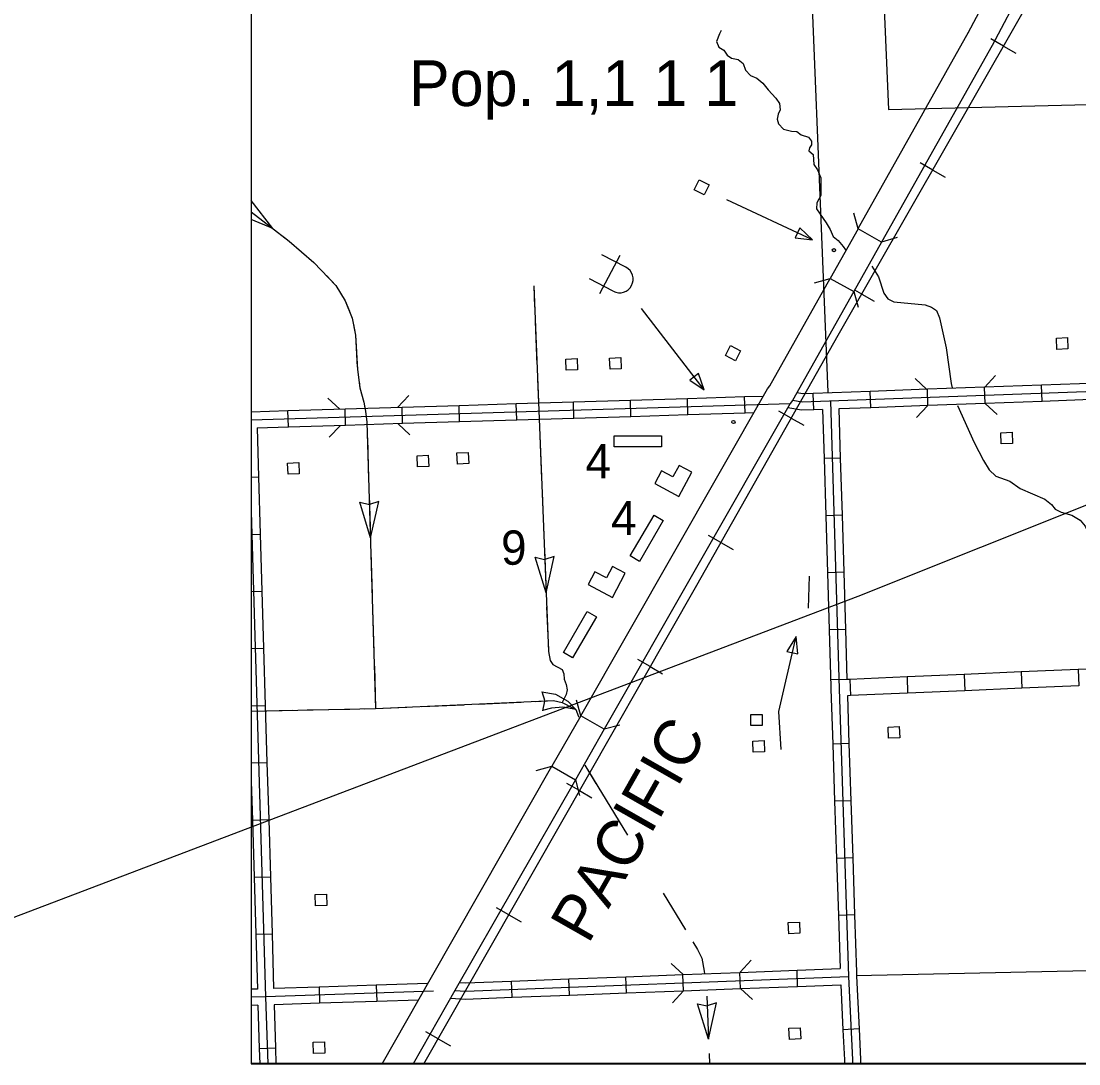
# Model space of a CAD drawing. Extents: x -0.3 to 2.65, y 0 to 1.9.
# Drawn here: x 0.3593 to 0.4763, y 0.1443 to 0.2596 of the extents above; entities that cross this region are included whole.
import ezdxf

# ---------------------------------------------------------------- set-up
doc = ezdxf.new("R2010")
doc.units = 0
for name, color, linetype in [('Default', 7, 'Continuous'), ('DSN_DRFT_DNC', 7, 'Continuous'), ('Level 12', 7, 'Continuous'), ('Level 14', 7, 'Continuous'), ('Level 15', 7, 'Continuous'), ('Level 19', 7, 'Continuous'), ('Level 20', 7, 'Continuous'), ('Level 27', 7, 'Continuous'), ('Level 28', 7, 'Continuous'), ('Level 29', 7, 'Continuous'), ('Level 30', 7, 'Continuous'), ('Level 31', 7, 'Continuous'), ('Level 32', 7, 'Continuous'), ('Level 6', 7, 'Continuous')]:
    doc.layers.add(name, color=color, linetype=linetype)

msp = doc.modelspace()

# ---------------------------------------------------------------- linework, layer by layer
at = {"layer": 'Default'}
msp.add_line((0.34423, 0.15508), (0.45189, 0.196), dxfattribs=at)
msp.add_lwpolyline([(0.45189, 0.196), (0.68371, 0.28858), (0.61638, 0.27038)], dxfattribs=at)
at = {"layer": 'DSN_DRFT_DNC'}
msp.add_lwpolyline([(0.38477, 0.54167), (1.0319, 0.54167), (1.0319, 0.1443), (0.38477, 0.1443)], close=True, dxfattribs=at)
at = {"layer": 'Level 12'}
for p, q in [((0.38713, 0.23666), (0.38476, 0.23975)), ((0.38476, 0.23848), (0.38713, 0.23666)), ((0.38713, 0.23666), (0.38476, 0.23764)), ((0.39675, 0.20639), (0.39782, 0.20614)), ((0.39794, 0.20246), (0.39675, 0.20639)), ((0.39888, 0.20646), (0.39783, 0.20614)), ((0.39794, 0.20246), (0.39888, 0.20646)), ((0.41615, 0.2003), (0.41721, 0.20006)), ((0.41737, 0.19638), (0.41615, 0.2003)), ((0.41827, 0.20038), (0.41723, 0.20006)), ((0.41737, 0.19638), (0.41827, 0.20038)), ((0.41691, 0.18544), (0.41724, 0.1844)), ((0.417, 0.18332), (0.41724, 0.18439)), ((0.43624, 0.15101), (0.43519, 0.15068)), ((0.43533, 0.147), (0.43624, 0.15101)), ((0.43411, 0.15092), (0.43518, 0.15068)), ((0.43533, 0.147), (0.43411, 0.15092)), ((0.4354, 0.14542), (0.43544, 0.14427))]:
    msp.add_line(p, q, dxfattribs=at)
for points in [[(0.38838, 0.2357), (0.38895, 0.23526), (0.39168, 0.2329), (0.39197, 0.2326)], [(0.39306, 0.23146), (0.39411, 0.23035), (0.39515, 0.22867), (0.39561, 0.22752)], [(0.416, 0.23031), (0.4161, 0.22794)], [(0.39606, 0.22602), (0.39629, 0.22484), (0.39648, 0.22131)], [(0.41616, 0.22636), (0.41635, 0.22163)], [(0.41642, 0.22005), (0.41653, 0.21736)], [(0.39668, 0.21974), (0.39678, 0.21905), (0.3972, 0.21744), (0.39733, 0.21677)], [(0.3976, 0.21351), (0.39774, 0.20878)], [(0.41667, 0.21374), (0.41686, 0.209)], [(0.39779, 0.2072), (0.39794, 0.20246)], [(0.41692, 0.20742), (0.41712, 0.20269)], [(0.39798, 0.20088), (0.39813, 0.19614)], [(0.41718, 0.20111), (0.41737, 0.19638)], [(0.39818, 0.19457), (0.39832, 0.18983)], [(0.41743, 0.1948), (0.41762, 0.19006)], [(0.41763, 0.18986), (0.41781, 0.18889), (0.41812, 0.18845), (0.41914, 0.18788), (0.41934, 0.18742), (0.41938, 0.18682), (0.41958, 0.18624), (0.41969, 0.18562), (0.41961, 0.18511), (0.41915, 0.18424), (0.41953, 0.18404), (0.42006, 0.18374), (0.42067, 0.18345), (0.42097, 0.18268), (0.42101, 0.18263)], [(0.39837, 0.18825), (0.39851, 0.18356)], [(0.4169, 0.18543), (0.41842, 0.18514), (0.41979, 0.18438), (0.42066, 0.18345), (0.41921, 0.18373), (0.41796, 0.18361), (0.41698, 0.18334)], [(0.39725, 0.18353), (0.39851, 0.18356), (0.40198, 0.18371)], [(0.40356, 0.18378), (0.40829, 0.18399)], [(0.40987, 0.18406), (0.4146, 0.18428)], [(0.41618, 0.18435), (0.4182, 0.18444), (0.41915, 0.18424)], [(0.38632, 0.18331), (0.38935, 0.18337)], [(0.39093, 0.18341), (0.39567, 0.1835)], [(0.42165, 0.17729), (0.42289, 0.17527)], [(0.43031, 0.16314), (0.43278, 0.1591)], [(0.43361, 0.15775), (0.43412, 0.15692), (0.43461, 0.15595), (0.43487, 0.15451), (0.4349, 0.15424)], [(0.43514, 0.15174), (0.43533, 0.147)]]:
    msp.add_lwpolyline(points, dxfattribs=at)
at = {"layer": 'Level 14'}
for points in [[(0.43675, 0.25856), (0.43655, 0.25819), (0.43624, 0.25733), (0.4365, 0.25671), (0.43705, 0.25637), (0.43739, 0.25583), (0.43789, 0.25549), (0.43863, 0.25534), (0.43916, 0.25492), (0.43943, 0.25417), (0.44, 0.25358), (0.44069, 0.25329), (0.44135, 0.25273), (0.44193, 0.25198), (0.44279, 0.25108), (0.4432, 0.25047), (0.44325, 0.24979), (0.44306, 0.24931), (0.44294, 0.24874), (0.44308, 0.24822), (0.44363, 0.24764), (0.44452, 0.24741), (0.44511, 0.24739), (0.4456, 0.24701), (0.44639, 0.24675), (0.44675, 0.24632), (0.44675, 0.2459), (0.44651, 0.24559), (0.44642, 0.24525), (0.44691, 0.24483), (0.44699, 0.24372), (0.4474, 0.24313), (0.44776, 0.24224), (0.44776, 0.24032), (0.44732, 0.2395), (0.4473, 0.23883), (0.44836, 0.23729), (0.44879, 0.23654), (0.44913, 0.23576), (0.44969, 0.23533), (0.45025, 0.23465), (0.45049, 0.23429)], [(0.38476, 0.23848), (0.38895, 0.23526), (0.39168, 0.2329), (0.39411, 0.23035), (0.39515, 0.22867), (0.39592, 0.22675), (0.39629, 0.22484), (0.3965, 0.22105), (0.39678, 0.21905), (0.3972, 0.21744), (0.39739, 0.21645), (0.39755, 0.21522), (0.39851, 0.18356)], [(0.38476, 0.23848), (0.38895, 0.23526), (0.39168, 0.2329), (0.39411, 0.23035), (0.39515, 0.22867), (0.39592, 0.22675), (0.39629, 0.22484), (0.3965, 0.22105), (0.39678, 0.21905), (0.3972, 0.21744), (0.39739, 0.21645), (0.39755, 0.21522), (0.39851, 0.18356)], [(0.45341, 0.23248), (0.45416, 0.23132), (0.45474, 0.2295), (0.45516, 0.22889), (0.45586, 0.22853), (0.45929, 0.22821), (0.46002, 0.22797), (0.46055, 0.22757), (0.46088, 0.22679), (0.46163, 0.22347), (0.46217, 0.21953), (0.46229, 0.21903)], [(0.416, 0.23031), (0.41763, 0.18986)], [(0.416, 0.23031), (0.41763, 0.18986)], [(0.4629, 0.21707), (0.46472, 0.21299), (0.46575, 0.211), (0.46638, 0.20997), (0.46714, 0.20926), (0.46867, 0.2087), (0.46982, 0.20789), (0.47256, 0.20672), (0.47328, 0.20613), (0.47369, 0.20563), (0.47436, 0.20528), (0.47552, 0.20495), (0.47644, 0.20439), (0.477, 0.20374), (0.47783, 0.20192), (0.47826, 0.20143), (0.47916, 0.20095)], [(0.38476, 0.18328), (0.39851, 0.18356), (0.4182, 0.18444), (0.41915, 0.18424)], [(0.38476, 0.18328), (0.39851, 0.18356), (0.4182, 0.18444), (0.41915, 0.18424)], [(0.42165, 0.17729), (0.42638, 0.16956)], [(0.42165, 0.17729), (0.42638, 0.16956)]]:
    msp.add_lwpolyline(points, dxfattribs=at)
at = {"layer": 'Level 15'}
for p, q in [((0.45962, 0.21707), (0.45955, 0.21887)), ((0.46593, 0.21731), (0.46586, 0.2191)), ((0.47224, 0.21754), (0.47218, 0.21933)), ((0.42676, 0.21588), (0.4267, 0.21767)), ((0.43307, 0.21607), (0.43302, 0.21786)), ((0.43939, 0.21626), (0.43933, 0.21806)), ((0.44699, 0.21661), (0.44692, 0.2184)), ((0.4533, 0.21684), (0.45324, 0.21863)), ((0.38476, 0.21548), (0.44439, 0.2173)), ((0.38476, 0.21639), (0.38881, 0.21651)), ((0.38887, 0.21472), (0.38881, 0.21651)), ((0.39518, 0.21491), (0.39513, 0.21671)), ((0.4015, 0.21511), (0.40144, 0.2169)), ((0.40781, 0.2153), (0.40776, 0.21709)), ((0.41413, 0.21549), (0.41407, 0.21729)), ((0.42044, 0.21568), (0.42039, 0.21748)), ((0.44992, 0.21126), (0.44812, 0.21121)), ((0.38476, 0.20916), (0.38556, 0.20918)), ((0.45011, 0.20495), (0.44831, 0.20489)), ((0.38476, 0.20283), (0.38575, 0.20286)), ((0.4503, 0.19863), (0.4485, 0.19858)), ((0.38476, 0.19651), (0.38593, 0.19655)), ((0.45049, 0.19232), (0.44869, 0.19226)), ((0.38476, 0.19019), (0.38612, 0.19023)), ((0.46361, 0.18734), (0.46369, 0.18554)), ((0.46992, 0.18761), (0.47, 0.18582)), ((0.47623, 0.18788), (0.47631, 0.18609)), ((0.45065, 0.18679), (0.44886, 0.18673)), ((0.45098, 0.18679), (0.45106, 0.185)), ((0.4573, 0.18707), (0.45737, 0.18527)), ((0.38476, 0.18387), (0.38631, 0.18392)), ((0.45088, 0.17969), (0.44909, 0.17963)), ((0.38476, 0.17755), (0.38649, 0.1776)), ((0.38476, 0.17548), (0.38489, 0.17123)), ((0.45109, 0.17337), (0.44929, 0.17332)), ((0.38489, 0.17123), (0.38668, 0.17129)), ((0.45129, 0.16706), (0.4495, 0.167)), ((0.38507, 0.16492), (0.38687, 0.16497)), ((0.4515, 0.16075), (0.44971, 0.16069)), ((0.38526, 0.1586), (0.38705, 0.15866)), ((0.4452, 0.15284), (0.44513, 0.15464)), ((0.41363, 0.15163), (0.41356, 0.15343)), ((0.41995, 0.15188), (0.41988, 0.15367)), ((0.42626, 0.15212), (0.42619, 0.15391)), ((0.43257, 0.15236), (0.4325, 0.15415)), ((0.43889, 0.1526), (0.43882, 0.15439)), ((0.38544, 0.15254), (0.38476, 0.15253)), ((0.39226, 0.15276), (0.39232, 0.15097)), ((0.39857, 0.15297), (0.39863, 0.15118)), ((0.38549, 0.15075), (0.38476, 0.15073)), ((0.452, 0.14813), (0.45021, 0.14805)), ((0.38564, 0.14597), (0.38744, 0.14603)), ((0.38564, 0.14597), (0.3857, 0.14427)), ((0.38744, 0.14603), (0.38749, 0.14427))]:
    msp.add_line(p, q, dxfattribs=at)
for points in [[(0.50863, 0.219), (0.50657, 0.21948), (0.50035, 0.21945), (0.44569, 0.21744), (0.44464, 0.21764)], [(0.45955, 0.21887), (0.45324, 0.21863)], [(0.46586, 0.2191), (0.45955, 0.21887)], [(0.47218, 0.21933), (0.46586, 0.2191)], [(0.47849, 0.21956), (0.47218, 0.21933)], [(0.42039, 0.21748), (0.4267, 0.21767)], [(0.4267, 0.21767), (0.43302, 0.21786)], [(0.43302, 0.21786), (0.43933, 0.21806)], [(0.43933, 0.21806), (0.44141, 0.21812)], [(0.44692, 0.2184), (0.44576, 0.21836), (0.44511, 0.21848)], [(0.45324, 0.21863), (0.44692, 0.2184)], [(0.47856, 0.21777), (0.47224, 0.21754)], [(0.38881, 0.21651), (0.39513, 0.21671)], [(0.39513, 0.21671), (0.40144, 0.2169)], [(0.40144, 0.2169), (0.40776, 0.21709)], [(0.40776, 0.21709), (0.41407, 0.21729)], [(0.41407, 0.21729), (0.42039, 0.21748)], [(0.44699, 0.21661), (0.44562, 0.21656), (0.44413, 0.21684)], [(0.44796, 0.21664), (0.44699, 0.21661)], [(0.44796, 0.21664), (0.44812, 0.21121)], [(0.44885, 0.21755), (0.4498, 0.18573), (0.45084, 0.15394), (0.45128, 0.14472), (0.45128, 0.14427)], [(0.4533, 0.21684), (0.44975, 0.21671)], [(0.44975, 0.21671), (0.44992, 0.21126)], [(0.45962, 0.21707), (0.4533, 0.21684)], [(0.46593, 0.21731), (0.45962, 0.21707)], [(0.47224, 0.21754), (0.46593, 0.21731)], [(0.40781, 0.2153), (0.41413, 0.21549)], [(0.41413, 0.21549), (0.42044, 0.21568)], [(0.42044, 0.21568), (0.42676, 0.21588)], [(0.42676, 0.21588), (0.43307, 0.21607)], [(0.43307, 0.21607), (0.43939, 0.21626)], [(0.43939, 0.21626), (0.44037, 0.21629)], [(0.3854, 0.21461), (0.38887, 0.21472)], [(0.3854, 0.21461), (0.38556, 0.20918)], [(0.38887, 0.21472), (0.39518, 0.21491)], [(0.39518, 0.21491), (0.4015, 0.21511)], [(0.4015, 0.21511), (0.40781, 0.2153)], [(0.44812, 0.21121), (0.44831, 0.20489)], [(0.44992, 0.21126), (0.45011, 0.20495)], [(0.38556, 0.20918), (0.38575, 0.20286)], [(0.38476, 0.20532), (0.38634, 0.15168), (0.38658, 0.14427)], [(0.44831, 0.20489), (0.4485, 0.19858)], [(0.45011, 0.20495), (0.4503, 0.19863)], [(0.38575, 0.20286), (0.38593, 0.19655)], [(0.4485, 0.19858), (0.44869, 0.19226)], [(0.4503, 0.19863), (0.45049, 0.19232)], [(0.38593, 0.19655), (0.38612, 0.19023)], [(0.44869, 0.19226), (0.44888, 0.18595)], [(0.45049, 0.19232), (0.45065, 0.18678)], [(0.38612, 0.19023), (0.38631, 0.18392)], [(0.46361, 0.18734), (0.4573, 0.18707)], [(0.46992, 0.18761), (0.46361, 0.18734)], [(0.47623, 0.18788), (0.46992, 0.18761)], [(0.48254, 0.18815), (0.47623, 0.18788)], [(0.45098, 0.18679), (0.45065, 0.18678)], [(0.4573, 0.18707), (0.45098, 0.18679)], [(0.47631, 0.18609), (0.47, 0.18582)], [(0.44888, 0.18595), (0.44889, 0.1857), (0.44909, 0.17963)], [(0.45106, 0.185), (0.45071, 0.18499)], [(0.45071, 0.18499), (0.45088, 0.17969)], [(0.45737, 0.18527), (0.45106, 0.185)], [(0.46369, 0.18554), (0.45737, 0.18527)], [(0.47, 0.18582), (0.46369, 0.18554)], [(0.38631, 0.18392), (0.38649, 0.1776)], [(0.44909, 0.17963), (0.44929, 0.17332)], [(0.45088, 0.17969), (0.45109, 0.17337)], [(0.38649, 0.1776), (0.38668, 0.17129)], [(0.44929, 0.17332), (0.4495, 0.167)], [(0.45109, 0.17337), (0.45129, 0.16706)], [(0.38489, 0.17123), (0.38507, 0.16492)], [(0.38668, 0.17129), (0.38687, 0.16497)], [(0.4495, 0.167), (0.44971, 0.16069)], [(0.45129, 0.16706), (0.4515, 0.16075)], [(0.38507, 0.16492), (0.38526, 0.1586)], [(0.38687, 0.16497), (0.38705, 0.15866)], [(0.44971, 0.16069), (0.4499, 0.15482)], [(0.4515, 0.16075), (0.45171, 0.15443)], [(0.38526, 0.1586), (0.38544, 0.15254)], [(0.38705, 0.15866), (0.38723, 0.15259)], [(0.43882, 0.15439), (0.44513, 0.15464)], [(0.44513, 0.15464), (0.4499, 0.15482)], [(0.40729, 0.15238), (0.40846, 0.15232), (0.45084, 0.15394)], [(0.40779, 0.15327), (0.40847, 0.15323), (0.41356, 0.15343)], [(0.41356, 0.15343), (0.41988, 0.15367)], [(0.41988, 0.15367), (0.42619, 0.15391)], [(0.42619, 0.15391), (0.4325, 0.15415)], [(0.4325, 0.15415), (0.43882, 0.15439)], [(0.45171, 0.15443), (0.45172, 0.15397), (0.452, 0.14813)], [(0.40492, 0.1523), (0.38634, 0.15168), (0.38476, 0.15165)], [(0.39226, 0.15276), (0.38723, 0.15259)], [(0.39857, 0.15297), (0.39226, 0.15276)], [(0.40429, 0.15316), (0.39857, 0.15297)], [(0.41995, 0.15188), (0.42626, 0.15212)], [(0.42626, 0.15212), (0.43257, 0.15236)], [(0.43257, 0.15236), (0.43889, 0.1526)], [(0.43889, 0.1526), (0.4452, 0.15284)], [(0.4452, 0.15284), (0.44997, 0.15302)], [(0.44997, 0.15302), (0.45021, 0.14805)], [(0.39232, 0.15097), (0.38729, 0.1508)], [(0.39863, 0.15118), (0.39232, 0.15097)], [(0.40325, 0.15133), (0.39863, 0.15118)], [(0.4068, 0.15152), (0.40846, 0.15144), (0.41363, 0.15163)], [(0.41363, 0.15163), (0.41995, 0.15188)], [(0.38549, 0.15075), (0.38564, 0.14597)], [(0.38729, 0.1508), (0.38744, 0.14603)], [(0.45021, 0.14805), (0.45037, 0.1447), (0.45037, 0.14427)], [(0.452, 0.14813), (0.45216, 0.14475), (0.45217, 0.14427)]]:
    msp.add_lwpolyline(points, dxfattribs=at)
at = {"layer": 'Level 19'}
for points in [[(0.43485, 0.24037), (0.43374, 0.24094), (0.43432, 0.24205), (0.43543, 0.24148)], [(0.44544, 0.23672), (0.44492, 0.23561), (0.44684, 0.23539)], [(0.43831, 0.22203), (0.43721, 0.22261), (0.43779, 0.22372), (0.43889, 0.22314)], [(0.47387, 0.22329), (0.47382, 0.22454), (0.47507, 0.22459), (0.47511, 0.22334)], [(0.42445, 0.22109), (0.4244, 0.22233), (0.42565, 0.22238), (0.42569, 0.22113)], [(0.4196, 0.22097), (0.41955, 0.22222), (0.4208, 0.22226), (0.42085, 0.22102)], [(0.43422, 0.22063), (0.43326, 0.21988), (0.43486, 0.2188)], [(0.42491, 0.21252), (0.42491, 0.21372), (0.43015, 0.21372), (0.43015, 0.21252)], [(0.46772, 0.21283), (0.46767, 0.21407), (0.46892, 0.21412), (0.46896, 0.21287)], [(0.40756, 0.21061), (0.40751, 0.21185), (0.40876, 0.2119), (0.40881, 0.21066)], [(0.38883, 0.20947), (0.38878, 0.21072), (0.39003, 0.21076), (0.39007, 0.20952)], [(0.40314, 0.21029), (0.40309, 0.21153), (0.40434, 0.21158), (0.40439, 0.21034)], [(0.42771, 0.19983), (0.42668, 0.20044), (0.42931, 0.20496), (0.43034, 0.20436)], [(0.42031, 0.18917), (0.41928, 0.18977), (0.42191, 0.1943), (0.42294, 0.1937)], [(0.44402, 0.18988), (0.44521, 0.18961), (0.44502, 0.19153)], [(0.44003, 0.18168), (0.44003, 0.18292), (0.44128, 0.18292), (0.44128, 0.18168)], [(0.45525, 0.18028), (0.4552, 0.18152), (0.45645, 0.18157), (0.4565, 0.18033)], [(0.44027, 0.17873), (0.44023, 0.17997), (0.44148, 0.18002), (0.44152, 0.17878)], [(0.39187, 0.16175), (0.39182, 0.16299), (0.39307, 0.16304), (0.39311, 0.1618)], [(0.44421, 0.15866), (0.44416, 0.15991), (0.44541, 0.15995), (0.44546, 0.15871)], [(0.44429, 0.14698), (0.44424, 0.14822), (0.44549, 0.14827), (0.44554, 0.14703)], [(0.39164, 0.14543), (0.39159, 0.14667), (0.39284, 0.14672), (0.39289, 0.14547)]]:
    msp.add_lwpolyline(points, close=True, dxfattribs=at)
for points in [[(0.44684, 0.23539), (0.43737, 0.23982)], [(0.43486, 0.2188), (0.42791, 0.22781)], [(0.44647, 0.19822), (0.44636, 0.19466)], [(0.44336, 0.17902), (0.44313, 0.18323), (0.44502, 0.19153)]]:
    msp.add_lwpolyline(points, dxfattribs=at)
for centre in [(0.44921, 0.23426), (0.4381, 0.21525)]:
    msp.add_circle(centre, 0.000179, dxfattribs=at)
at = {"layer": 'Level 20'}
for points in [[(0.44598, 0.28113), (0.44855, 0.21854)], [(0.51498, 0.15538), (0.45169, 0.15402)]]:
    msp.add_lwpolyline(points, dxfattribs=at)
at = {"layer": 'Level 27'}
msp.add_line((0.41801, 0.17718), (0.42061, 0.17569), dxfattribs=at)
for points in [[(0.46406, 0.25829), (0.46746, 0.2647), (0.46855, 0.26669), (0.469, 0.26749), (0.46918, 0.26798), (0.46942, 0.26902), (0.46962, 0.27057), (0.46967, 0.27218)], [(0.47266, 0.27209), (0.47261, 0.27033), (0.47237, 0.26848), (0.47205, 0.26712), (0.47173, 0.26624), (0.47117, 0.26524), (0.47009, 0.26328), (0.46671, 0.25689)], [(0.45189, 0.23665), (0.4641, 0.25836)], [(0.46671, 0.25689), (0.45448, 0.23515)], [(0.45188, 0.23663), (0.44879, 0.23113)], [(0.45449, 0.23516), (0.45188, 0.23663)], [(0.45448, 0.23515), (0.45142, 0.2297)], [(0.42121, 0.18277), (0.44187, 0.21892), (0.44211, 0.21926), (0.44879, 0.23113)], [(0.4488, 0.23114), (0.4514, 0.22967)], [(0.45142, 0.2297), (0.44464, 0.21764), (0.44439, 0.2173), (0.4238, 0.18127)], [(0.4212, 0.18276), (0.41802, 0.17719)], [(0.4238, 0.18127), (0.4212, 0.18275)], [(0.4238, 0.18127), (0.42062, 0.1757)], [(0.39923, 0.14427), (0.40469, 0.15386), (0.41802, 0.17719)], [(0.42061, 0.17569), (0.40729, 0.15238), (0.40268, 0.14427)]]:
    msp.add_lwpolyline(points, dxfattribs=at)
at = {"layer": 'Level 28'}
for p, q in [((0.46797, 0.25683), (0.46659, 0.25762)), ((0.46797, 0.25683), (0.46934, 0.25605)), ((0.46014, 0.24312), (0.45876, 0.2439)), ((0.46014, 0.24312), (0.46151, 0.24233)), ((0.45231, 0.2294), (0.45152, 0.22985)), ((0.45231, 0.2294), (0.45368, 0.22862)), ((0.4445, 0.21567), (0.44312, 0.21645)), ((0.4445, 0.21567), (0.44587, 0.21489)), ((0.4367, 0.20193), (0.43533, 0.20271)), ((0.4367, 0.20193), (0.43808, 0.20115)), ((0.42888, 0.18821), (0.42751, 0.18899)), ((0.42888, 0.18821), (0.43026, 0.18742)), ((0.42106, 0.17449), (0.41968, 0.17527)), ((0.42106, 0.17449), (0.42243, 0.1737)), ((0.41324, 0.16076), (0.41187, 0.16154)), ((0.41324, 0.16076), (0.41461, 0.15998)), ((0.40543, 0.14703), (0.40406, 0.14781)), ((0.40543, 0.14703), (0.4068, 0.14625))]:
    msp.add_line(p, q, dxfattribs=at)
for points in [[(0.40386, 0.14427), (0.4188, 0.17053), (0.43403, 0.19722), (0.4497, 0.22484), (0.4732, 0.266), (0.47682, 0.27303), (0.47817, 0.27549), (0.4797, 0.2782), (0.48111, 0.28039), (0.48332, 0.28357), (0.48511, 0.28592), (0.48761, 0.28907), (0.49328, 0.29577), (0.49996, 0.30333), (0.50451, 0.30855), (0.53786, 0.34671), (0.60158, 0.41969), (0.64921, 0.4745), (0.68992, 0.52123)], [(0.40386, 0.14427), (0.4188, 0.17053), (0.43403, 0.19722), (0.4497, 0.22484), (0.4732, 0.266)], [(0.40386, 0.14427), (0.4188, 0.17053), (0.43403, 0.19722), (0.4497, 0.22484), (0.4732, 0.266)], [(0.40386, 0.14427), (0.4188, 0.17053), (0.43403, 0.19722), (0.4497, 0.22484), (0.4732, 0.266)], [(0.40386, 0.14427), (0.4188, 0.17053), (0.43403, 0.19722), (0.4497, 0.22484), (0.4732, 0.266)]]:
    msp.add_lwpolyline(points, dxfattribs=at)
at = {"layer": 'Level 29'}
for p, q in [((0.45954, 0.21795), (0.45954, 0.21795)), ((0.46591, 0.21819), (0.46591, 0.21819))]:
    msp.add_line(p, q, dxfattribs=at)
for points in [[(0.45819, 0.22007), (0.4595, 0.21885)], [(0.46588, 0.21908), (0.4671, 0.2204)], [(0.39324, 0.2179), (0.39455, 0.21667)], [(0.40095, 0.21687), (0.40218, 0.21818)], [(0.45957, 0.21705), (0.45835, 0.21574)], [(0.46726, 0.21607), (0.46595, 0.21729)], [(0.39461, 0.21488), (0.39338, 0.21357)], [(0.40231, 0.21384), (0.401, 0.21507)], [(0.43885, 0.15441), (0.44007, 0.15573)], [(0.43122, 0.15538), (0.43253, 0.15416)], [(0.43259, 0.15235), (0.43137, 0.15103)], [(0.4402, 0.15138), (0.43888, 0.1526)]]:
    msp.add_lwpolyline(points, dxfattribs=at)
at = {"layer": 'Level 30'}
for points in [[(0.45188, 0.23663), (0.4514, 0.23836)], [(0.45622, 0.23565), (0.45449, 0.23516)], [(0.44707, 0.23066), (0.4488, 0.23114)], [(0.4514, 0.22967), (0.45189, 0.22795)], [(0.4212, 0.18275), (0.42073, 0.18449)], [(0.42553, 0.18174), (0.4238, 0.18127)], [(0.41628, 0.17671), (0.41801, 0.17718)], [(0.42061, 0.17569), (0.42108, 0.17396)]]:
    msp.add_lwpolyline(points, dxfattribs=at)
at = {"layer": 'Level 31'}
for points in [[(0.43207, 0.20702), (0.4335, 0.20971), (0.43208, 0.21046), (0.4314, 0.20919), (0.43014, 0.20986), (0.42939, 0.20845)], [(0.42471, 0.19585), (0.42613, 0.19854), (0.42471, 0.19929), (0.42404, 0.19802), (0.42277, 0.19869), (0.42202, 0.19728)]]:
    msp.add_lwpolyline(points, close=True, dxfattribs=at)
at = {"layer": 'Level 32'}
for p, q in [((0.42333, 0.22948), (0.42555, 0.23372)), ((0.42619, 0.23237), (0.42354, 0.23375)), ((0.42481, 0.22972), (0.42216, 0.2311))]:
    msp.add_line(p, q, dxfattribs=at)
msp.add_arc((0.4255, 0.23104), 0.0015, 242.4615, 62.4615, dxfattribs=at)
at = {"layer": 'Level 6'}
for p, q in [((0.38476, 0.54164), (0.38476, 0.14427)), ((0.38476, 0.14427), (1.03189, 0.14427))]:
    msp.add_line(p, q, dxfattribs=at)
msp.add_lwpolyline([(0.45459, 0.26528), (0.45524, 0.24982), (0.48028, 0.25043)], dxfattribs=at)

# ---------------------------------------------------------------- texts
at = {"layer": 'Level 19'}
for s, p in [('4', (0.42173, 0.20902)), ('4', (0.42456, 0.20274)), ('9', (0.41239, 0.19947))]:
    msp.add_text(s, height=0.00379, dxfattribs=at).set_placement(p)
at = {"layer": 'Level 28'}
msp.add_text('PACIFIC', height=0.005055, rotation=60.3781, dxfattribs=at).set_placement((0.42204, 0.15742))
at = {"layer": 'Level 6'}
msp.add_text('Pop. 1,1 1 1', height=0.0050545, dxfattribs=at).set_placement((0.40219, 0.2502))

doc.saveas('drawing.dxf')
